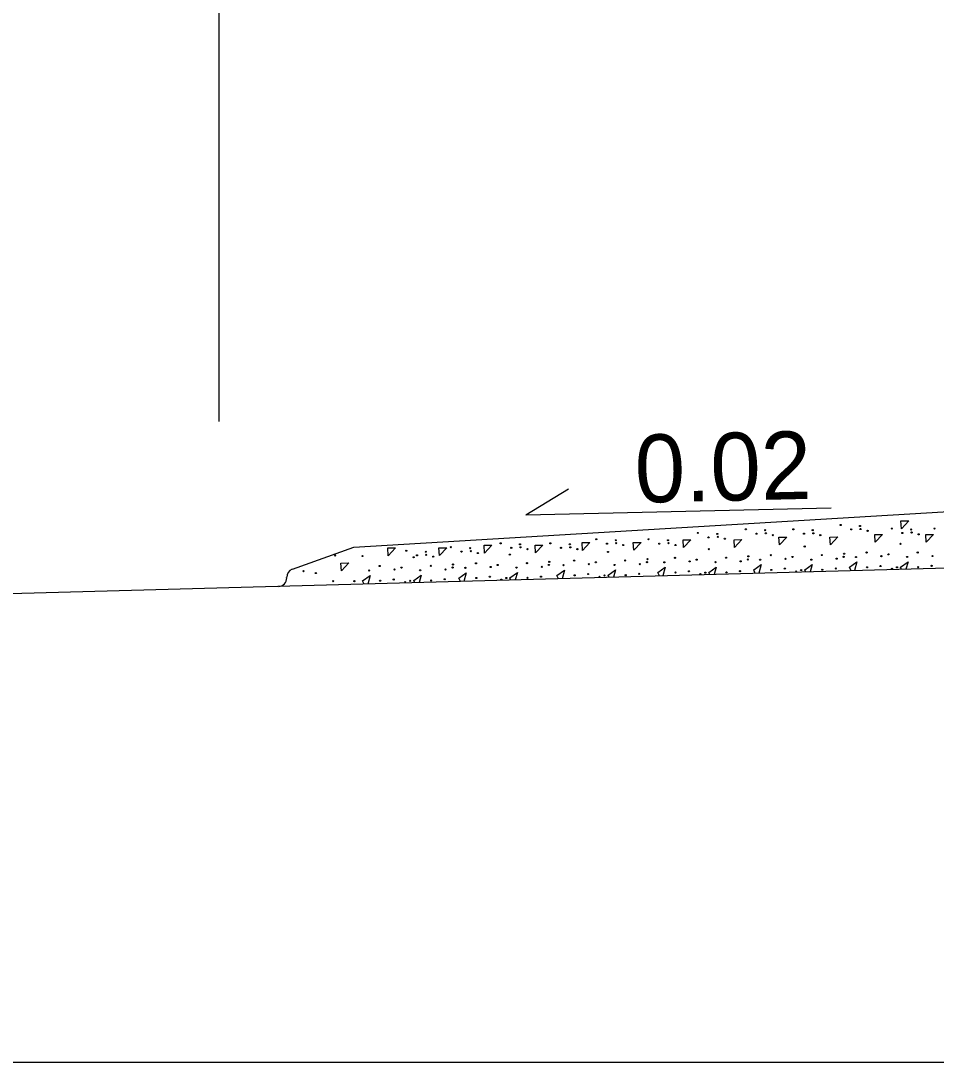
# Model space of a CAD drawing. Extents: x 1904401 to 1905163, y 193929 to 194736.
# Drawn here: x 1904569.23 to 1904579.35, y 194429.04 to 194440.55 of the extents above; entities that cross this region are included whole.
import ezdxf

# ---------------------------------------------------------------- set-up
doc = ezdxf.new("R2010")
doc.units = 0
for name, color, linetype in [('Prop Dimension', 7, 'Continuous'), ('Prop Dimension Text', 7, 'Continuous'), ('Typical Arrow Superelevation CELL', 7, 'Continuous'), ('Typical Curb CELL', 7, 'Continuous'), ('Typical Pavement Slope CELL', 7, 'Continuous'), ('Typical Sidewalk and Rail CELL', 7, 'Continuous')]:
    doc.layers.add(name, color=color, linetype=linetype)

msp = doc.modelspace()

# ---------------------------------------------------------------- linework, layer by layer
at = {"layer": 'Prop Dimension'}
msp.add_line((1904571.422, 194451.534), (1904571.422, 194436.118), dxfattribs=at)
at = {"layer": 'Typical Arrow Superelevation CELL'}
for q in [(1904575.287, 194435.374), (1904578.193, 194435.165)]:
    msp.add_line((1904574.818, 194435.088), q, dxfattribs=at)
at = {"layer": 'Typical Curb CELL'}
for p, q in [((1904572.916, 194434.729), (1904580.206, 194435.168)), ((1904578.965, 194435.02), (1904579.051, 194435.02)), ((1904578.97, 194434.934), (1904578.965, 194435.02)), ((1904579.051, 194435.02), (1904578.97, 194434.934)), ((1904578.675, 194434.87), (1904578.761, 194434.87)), ((1904578.68, 194434.784), (1904578.675, 194434.87)), ((1904578.761, 194434.87), (1904578.68, 194434.784)), ((1904579.24, 194434.872), (1904579.326, 194434.872)), ((1904579.245, 194434.785), (1904579.24, 194434.872)), ((1904579.326, 194434.872), (1904579.245, 194434.785)), ((1904574.355, 194434.751), (1904574.441, 194434.752)), ((1904574.36, 194434.665), (1904574.355, 194434.751)), ((1904574.441, 194434.752), (1904574.36, 194434.665)), ((1904574.92, 194434.753), (1904575.006, 194434.753)), ((1904574.925, 194434.667), (1904574.92, 194434.753)), ((1904575.006, 194434.753), (1904574.925, 194434.667)), ((1904575.44, 194434.781), (1904575.526, 194434.781)), ((1904575.445, 194434.695), (1904575.44, 194434.781)), ((1904575.526, 194434.781), (1904575.445, 194434.695)), ((1904576.005, 194434.783), (1904576.091, 194434.783)), ((1904576.01, 194434.697), (1904576.005, 194434.783)), ((1904576.091, 194434.783), (1904576.01, 194434.697)), ((1904576.555, 194434.812), (1904576.641, 194434.812)), ((1904576.56, 194434.726), (1904576.555, 194434.812)), ((1904576.641, 194434.812), (1904576.56, 194434.726)), ((1904577.12, 194434.813), (1904577.206, 194434.814)), ((1904577.125, 194434.727), (1904577.12, 194434.813)), ((1904577.206, 194434.814), (1904577.125, 194434.727)), ((1904577.615, 194434.841), (1904577.701, 194434.841)), ((1904577.62, 194434.755), (1904577.615, 194434.841)), ((1904577.701, 194434.841), (1904577.62, 194434.755)), ((1904578.18, 194434.842), (1904578.266, 194434.843)), ((1904578.185, 194434.756), (1904578.18, 194434.842)), ((1904578.266, 194434.843), (1904578.185, 194434.756)), ((1904572.235, 194434.487), (1904572.916, 194434.729)), ((1904573.291, 194434.722), (1904573.377, 194434.722)), ((1904573.296, 194434.636), (1904573.291, 194434.722)), ((1904573.377, 194434.722), (1904573.296, 194434.636)), ((1904573.856, 194434.724), (1904573.942, 194434.724)), ((1904573.861, 194434.638), (1904573.856, 194434.724)), ((1904573.942, 194434.724), (1904573.861, 194434.638)), ((1904572.772, 194434.554), (1904572.858, 194434.556)), ((1904572.779, 194434.468), (1904572.772, 194434.554)), ((1904572.858, 194434.556), (1904572.779, 194434.468)), ((1904576.276, 194434.45), (1904576.358, 194434.508)), ((1904576.358, 194434.508), (1904576.332, 194434.413)), ((1904576.841, 194434.451), (1904576.923, 194434.51)), ((1904576.923, 194434.51), (1904576.901, 194434.429)), ((1904577.336, 194434.479), (1904577.418, 194434.538)), ((1904577.418, 194434.538), (1904577.392, 194434.442)), ((1904577.901, 194434.48), (1904577.983, 194434.539)), ((1904577.983, 194434.539), (1904577.961, 194434.458)), ((1904578.396, 194434.508), (1904578.478, 194434.567)), ((1904578.413, 194434.47), (1904578.396, 194434.508)), ((1904578.478, 194434.567), (1904578.452, 194434.471)), ((1904578.961, 194434.51), (1904579.043, 194434.568)), ((1904578.972, 194434.485), (1904578.961, 194434.51)), ((1904579.043, 194434.568), (1904579.02, 194434.487)), ((1904572.172, 194434.392), (1904572.172, 194434.397)), ((1904573.012, 194434.36), (1904573.094, 194434.419)), ((1904573.094, 194434.419), (1904573.068, 194434.323)), ((1904573.577, 194434.362), (1904573.659, 194434.42)), ((1904573.659, 194434.42), (1904573.636, 194434.339)), ((1904574.076, 194434.389), (1904574.158, 194434.448)), ((1904574.158, 194434.448), (1904574.132, 194434.352)), ((1904574.641, 194434.391), (1904574.723, 194434.45)), ((1904574.723, 194434.45), (1904574.7, 194434.368)), ((1904575.161, 194434.419), (1904575.243, 194434.478)), ((1904575.178, 194434.381), (1904575.161, 194434.419)), ((1904575.243, 194434.478), (1904575.217, 194434.382)), ((1904575.726, 194434.421), (1904575.808, 194434.479)), ((1904575.737, 194434.397), (1904575.726, 194434.421)), ((1904575.808, 194434.479), (1904575.786, 194434.398)), ((1904576.293, 194434.412), (1904576.276, 194434.45)), ((1904576.852, 194434.427), (1904576.841, 194434.451)), ((1904577.353, 194434.441), (1904577.336, 194434.479)), ((1904577.912, 194434.456), (1904577.901, 194434.48)), ((1904573.029, 194434.322), (1904573.012, 194434.36)), ((1904573.588, 194434.338), (1904573.577, 194434.362)), ((1904574.093, 194434.351), (1904574.076, 194434.389)), ((1904574.652, 194434.367), (1904574.641, 194434.391))]:
    msp.add_line(p, q, dxfattribs=at)
for centre in [(1904578.298, 194434.976), (1904578.512, 194434.965), (1904576.719, 194434.888), (1904576.934, 194434.877), (1904577.25, 194434.928), (1904577.367, 194434.879), (1904577.464, 194434.918), (1904577.47, 194434.884), (1904577.548, 194434.864), (1904577.775, 194434.928), (1904577.892, 194434.879), (1904577.989, 194434.918), (1904577.995, 194434.884), (1904578.073, 194434.864), (1904578.415, 194434.927), (1904578.518, 194434.931), (1904578.596, 194434.911), (1904578.863, 194434.936), (1904578.98, 194434.887), (1904579.077, 194434.926), (1904579.083, 194434.892), (1904579.161, 194434.872), (1904579.336, 194434.936), (1904573.988, 194434.731), (1904574.538, 194434.773), (1904574.753, 194434.762), (1904575.088, 194434.773), (1904575.303, 194434.762), (1904575.596, 194434.818), (1904575.714, 194434.769), (1904575.811, 194434.807), (1904575.816, 194434.774), (1904575.894, 194434.754), (1904576.174, 194434.818), (1904576.292, 194434.769), (1904576.389, 194434.807), (1904576.394, 194434.774), (1904576.472, 194434.754), (1904576.837, 194434.839), (1904576.939, 194434.844), (1904577.017, 194434.824), (1904577.9, 194434.738), (1904578.96, 194434.767), (1904572.708, 194434.639), (1904573.01, 194434.632), (1904573.495, 194434.691), (1904573.576, 194434.619), (1904573.613, 194434.641), (1904573.71, 194434.68), (1904573.715, 194434.646), (1904573.793, 194434.626), (1904574.105, 194434.681), (1904574.202, 194434.72), (1904574.208, 194434.686), (1904574.286, 194434.666), (1904574.64, 194434.648), (1904574.656, 194434.724), (1904574.758, 194434.729), (1904574.836, 194434.709), (1904575.206, 194434.724), (1904575.309, 194434.729), (1904575.387, 194434.709), (1904575.726, 194434.678), (1904576.841, 194434.709), (1904577.277, 194434.629), (1904577.525, 194434.642), (1904577.766, 194434.622), (1904578.09, 194434.643), (1904578.331, 194434.624), (1904578.336, 194434.658), (1904578.468, 194434.621), (1904578.585, 194434.671), (1904578.748, 194434.631), (1904578.826, 194434.651), (1904579.033, 194434.622), (1904579.15, 194434.672), (1904579.313, 194434.632), (1904573.201, 194434.523), (1904573.442, 194434.504), (1904573.766, 194434.525), (1904574.007, 194434.505), (1904574.012, 194434.539), (1904574.148, 194434.502), (1904574.265, 194434.552), (1904574.428, 194434.512), (1904574.506, 194434.533), (1904574.713, 194434.504), (1904574.83, 194434.554), (1904574.993, 194434.514), (1904575.071, 194434.534), (1904575.076, 194434.568), (1904575.233, 194434.532), (1904575.351, 194434.582), (1904575.513, 194434.542), (1904575.591, 194434.563), (1904575.798, 194434.534), (1904575.916, 194434.584), (1904576.078, 194434.543), (1904576.156, 194434.564), (1904576.162, 194434.598), (1904576.348, 194434.563), (1904576.466, 194434.613), (1904576.628, 194434.573), (1904576.706, 194434.593), (1904576.913, 194434.564), (1904577.031, 194434.614), (1904577.193, 194434.574), (1904577.271, 194434.595), (1904577.408, 194434.592), (1904577.688, 194434.602), (1904577.973, 194434.593), (1904578.253, 194434.603), (1904578.59, 194434.508), (1904578.739, 194434.522), (1904578.921, 194434.507), (1904579.155, 194434.51), (1904579.304, 194434.524), (1904572.358, 194434.465), (1904572.494, 194434.445), (1904573.084, 194434.473), (1904573.364, 194434.483), (1904573.649, 194434.475), (1904573.929, 194434.484), (1904574.27, 194434.39), (1904574.419, 194434.404), (1904574.601, 194434.389), (1904574.835, 194434.391), (1904574.984, 194434.405), (1904575.356, 194434.42), (1904575.505, 194434.433), (1904575.632, 194434.402), (1904575.686, 194434.418), (1904575.921, 194434.421), (1904576.07, 194434.435), (1904576.471, 194434.45), (1904576.62, 194434.464), (1904576.747, 194434.433), (1904576.801, 194434.449), (1904577.036, 194434.452), (1904577.185, 194434.466), (1904577.531, 194434.479), (1904577.68, 194434.493), (1904577.806, 194434.462), (1904577.861, 194434.478), (1904578.095, 194434.481), (1904578.245, 194434.495), (1904578.866, 194434.491), (1904572.686, 194434.354), (1904572.921, 194434.355), (1904573.206, 194434.36), (1904573.356, 194434.374), (1904573.482, 194434.343), (1904573.537, 194434.359), (1904573.771, 194434.362), (1904573.92, 194434.376), (1904574.546, 194434.372)]:
    msp.add_circle(centre, 0.00635, dxfattribs=at)
for centre, start, end in [((1904572.079, 194434.39), 271.0769, 1.0769), ((1904572.266, 194434.399), 109.5118, 181.0769)]:
    msp.add_arc(centre, 0.0937, start, end, dxfattribs=at)
at = {"layer": 'Typical Pavement Slope CELL'}
msp.add_line((1904579.661, 194434.504), (1904557.583, 194433.898), dxfattribs=at)
at = {"layer": 'Typical Sidewalk and Rail CELL'}
msp.add_line((1904550.75, 194429.038), (1904609.594, 194429.038), dxfattribs=at)

# ---------------------------------------------------------------- texts
at = {"layer": 'Prop Dimension Text'}
msp.add_text('0.02', height=0.7499, rotation=1.2959, dxfattribs=at).set_placement((1904576.029, 194435.221))

doc.saveas('drawing.dxf')
